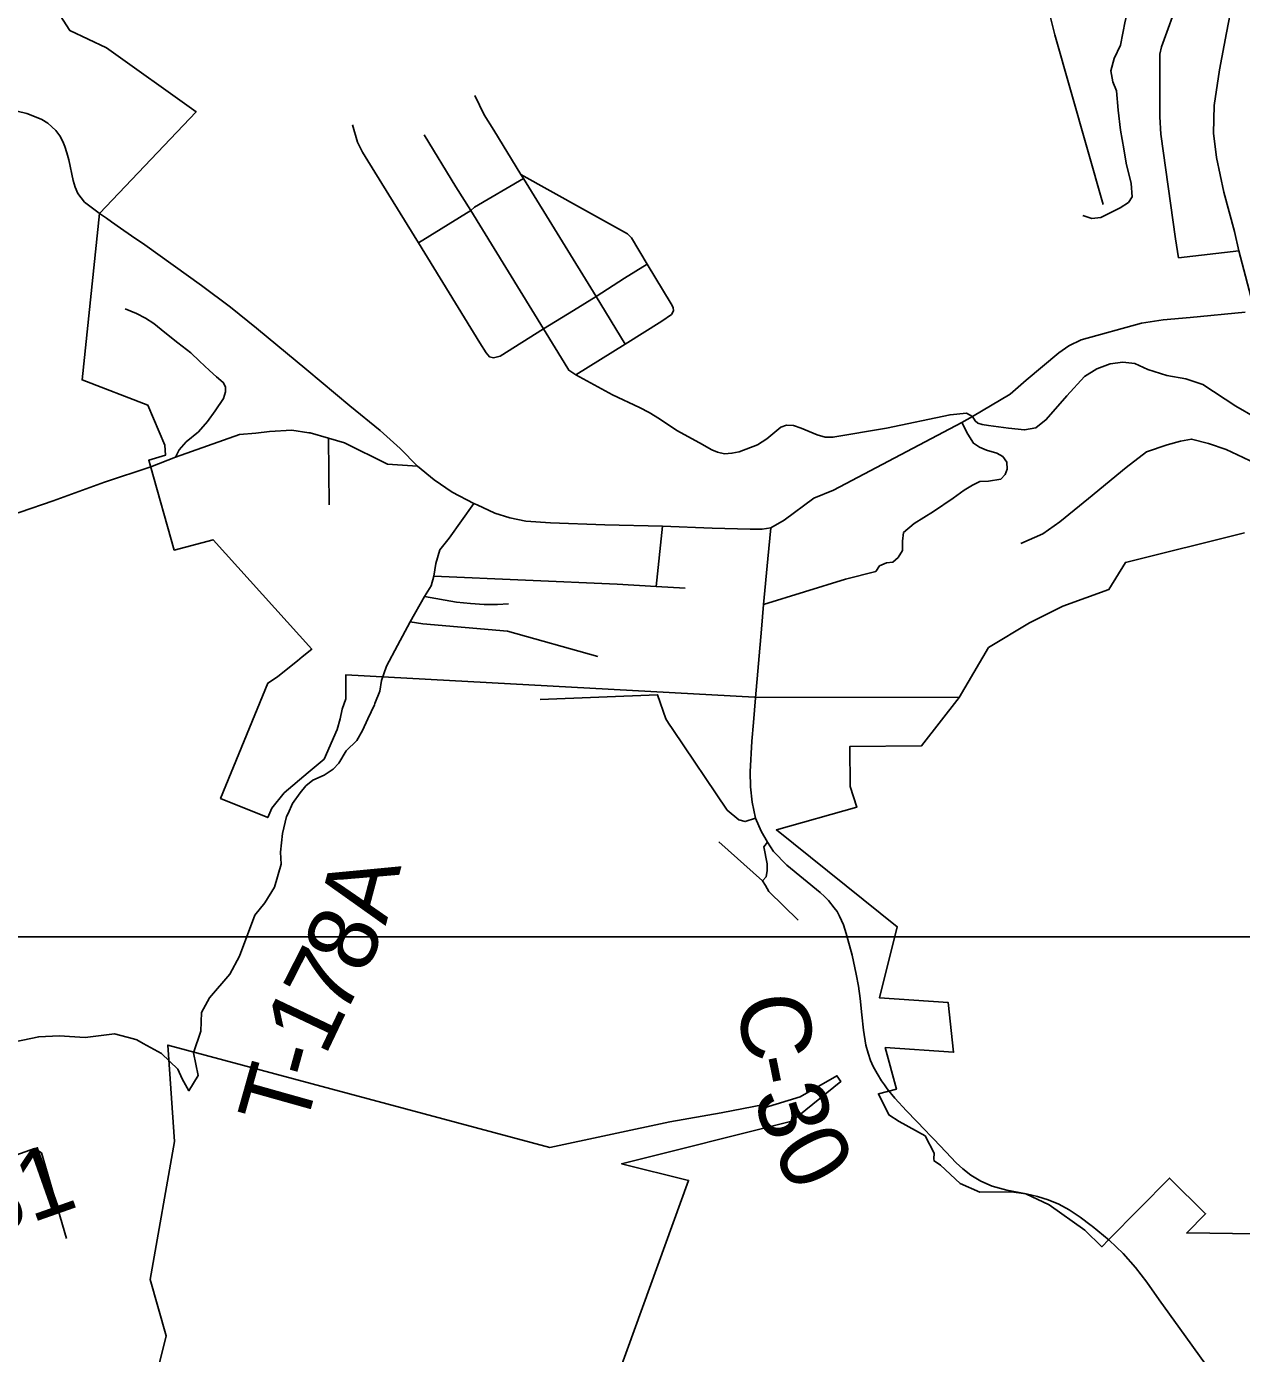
# Model space of a CAD drawing. Extents: x 2402298 to 2498138, y 789485 to 950881.
# Drawn here: x 2487007 to 2492231, y 857480 to 863186 of the extents above; entities that cross this region are included whole.
import ezdxf

# ---------------------------------------------------------------- set-up
doc = ezdxf.new("R2010")
doc.units = 0
for name, color, linetype in [('GM_X_City_Street', 7, 'Continuous'), ('GM_X_Corporation', 7, 'Continuous'), ('GM_X_County_Road', 7, 'Continuous'), ('GM_X_County_Road_Text', 7, 'Continuous'), ('GM_X_Township_Road', 7, 'Continuous'), ('GM_X_Township_Road_Text', 7, 'Continuous'), ('SH_Text', 7, 'Continuous')]:
    doc.layers.add(name, color=color, linetype=linetype)

msp = doc.modelspace()

# ---------------------------------------------------------------- linework, layer by layer
at = {"layer": 'GM_X_City_Street'}
for p, q in [((2491960.8, 862191.7), (2492219.7, 862221.5)), ((2488308.5, 861128.4), (2488305.2, 861415.9)), ((2489713.9, 860777.3), (2489742, 861037.1)), ((2490176.7, 860700), (2490528.2, 860808.9))]:
    msp.add_line(p, q, dxfattribs=at)
for points in [[(2491710.1, 862406), (2491746, 862429), (2491761.9, 862453.6), (2491757.2, 862510.5), (2491736.2, 862597.7), (2491725, 862660.2), (2491711.6, 862740.2), (2491700.9, 862825.8), (2491694.2, 862909.4), (2491678.8, 862948.3), (2491669.6, 862995.5), (2491684.5, 863048.8), (2491711.1, 863105.7), (2491731.6, 863208.3), (2491770.6, 863362), (2491857.7, 863639.9), (2491891.6, 863752.7), (2491894.6, 863789.6), (2491884.4, 863817.3), (2492057.7, 864297.1), (2492090.9, 864310.9)], [(2491637.3, 862419.8), (2491428.6, 863149.3), (2491392.8, 863292.8), (2491373.8, 863335.9), (2491315.3, 863386.7), (2491242.6, 863455.9), (2491216.9, 863490.2), (2491208.2, 863523), (2491254.2, 863763)], [(2491960.8, 862191.7), (2491947.4, 862272.2), (2491884.9, 862723.3), (2491880.8, 862797.1), (2491879.8, 862875), (2491880.8, 863067.3), (2491886.9, 863098.5), (2492115.1, 863727.6)], [(2492286.3, 861969.7), (2492219.7, 862221.5), (2492201.7, 862303.9), (2492155.6, 862473.1), (2492123.8, 862621.8), (2492111.5, 862727.4), (2492113.5, 862846.3), (2492137.1, 862999.1), (2492166.9, 863159), (2492191.5, 863284.6), (2492226.3, 863403.1), (2492309.2, 863653.8)], [(2489581.5, 861820.1), (2489457.1, 862024.7), (2489144.6, 862532.5), (2489132.7, 862549.1), (2489015.9, 862740.2), (2488975.1, 862806), (2488934.2, 862889.5)], [(2488956, 861826.2), (2488692.7, 862256.2), (2488475.2, 862608.4), (2488452.2, 862645.9), (2488430.7, 862688.9), (2488409.2, 862762.9)], [(2491075.5, 861508.6), (2491048.8, 861522.4), (2490978.6, 861516), (2490704.7, 861458.5), (2490474.3, 861419.2), (2490442, 861419.8), (2490407.3, 861430.2), (2490338.5, 861457.9), (2490304.4, 861470.5), (2490274.6, 861472), (2490250.9, 861463.4), (2490233.4, 861448.1), (2490190.7, 861413.3), (2490150.8, 861387.5), (2490071.8, 861357.4), (2490040.2, 861350.4), (2490008.2, 861348.8), (2489978.4, 861355), (2489953.8, 861365.7), (2489900.4, 861396.1), (2489803.9, 861448.7), (2489729, 861498.1), (2489684.4, 861526.4), (2489642.6, 861547.9), (2489526.8, 861601.4), (2489369.5, 861688.5), (2489339.7, 861707.7), (2489319.1, 861740.8), (2489229.4, 861886.1), (2488917.9, 862394.3), (2488853.4, 862496.9), (2488717.6, 862720.5)], [(2488692.7, 862256.2), (2488917.9, 862394.3), (2488933.3, 862408.7), (2489144.6, 862532.5)], [(2489369.5, 861688.5), (2489581.5, 861820.1), (2489739.4, 861918.4), (2489780, 861947.6), (2489788.6, 861963.3), (2489787, 861977.1), (2489779.4, 861993.7), (2489676.3, 862163.4), (2489608.8, 862277.5), (2489591, 862294.1), (2489397.8, 862401.3), (2489132.7, 862549.1)], [(2491548.6, 862373.7), (2491588.1, 862360.3), (2491626, 862363.9), (2491673.2, 862387), (2491710.1, 862406)], [(2488956, 861826.2), (2488983, 861782.9), (2488997.2, 861765.4), (2489015.6, 861761.7), (2489043.3, 861768.2), (2489229.4, 861886.1), (2489358.8, 861964.8), (2489457.1, 862024.7), (2489577.8, 862103.4), (2489676.3, 862163.4)], [(2487430.7, 861971.2), (2487479.5, 861951), (2487518.2, 861931.3), (2487554.2, 861908), (2487601.5, 861869.9), (2487657.4, 861825), (2487713.6, 861782.3), (2487751.4, 861746.7), (2487793.2, 861706.4), (2487824.5, 861679.4), (2487853.1, 861655.4), (2487862.3, 861637), (2487862, 861614.3), (2487853.4, 861585.7), (2487818.4, 861533.2), (2487784.9, 861486.8), (2487745.9, 861442.5), (2487693.4, 861399.2), (2487663.9, 861365.7), (2487648.2, 861333.5)], [(2492292.4, 861504.7), (2492206.7, 861552.8), (2492065.1, 861647), (2491991.6, 861671.4), (2491909.9, 861685.5), (2491828.2, 861711.3), (2491772.2, 861736.8), (2491721.9, 861742.7), (2491666.2, 861735.9), (2491610, 861713.2), (2491556.6, 861681.2), (2491480.4, 861597.1), (2491391.9, 861495.7), (2491346.5, 861460), (2491298.5, 861450.8), (2491229.1, 861458.8), (2491144.3, 861470.5), (2491117, 861473.9), (2491098.3, 861479.6), (2491087, 861489.9), (2491075.5, 861508.6)], [(2490528.2, 860808.9), (2490659, 860842.4), (2490675.1, 860866.3), (2490704.6, 860879), (2490731.7, 860882.9), (2490755.3, 860902.6), (2490773.8, 860932.3), (2490773.4, 860972.3), (2490777.7, 861009.8), (2490824.6, 861048.9), (2490906.8, 861100.1), (2490991.6, 861157.8), (2491039.7, 861191.3), (2491074.8, 861212.9), (2491106.9, 861228.8), (2491144.3, 861230.9), (2491196.4, 861239.5), (2491215.3, 861259.8), (2491223.9, 861282.6), (2491222.6, 861312.3), (2491205.4, 861336.3), (2491179.6, 861351), (2491135.7, 861364.3), (2491104.7, 861377.2), (2491079.3, 861394), (2491054.8, 861433.2), (2491029.4, 861483.1)], [(2491282, 860962.7), (2491377.7, 861004.5), (2491450.4, 861056.3), (2491574.1, 861156.5), (2491735.2, 861289.3), (2491823.6, 861357.2), (2491912.4, 861386.6), (2491969.3, 861403.1), (2492016.6, 861411.5), (2492089.3, 861392.4), (2492165.3, 861367.1), (2492239, 861331.9), (2492298.5, 861303.3), (2492345.5, 861274.3), (2492368.6, 861255.9)], [(2488532.9, 860373.3), (2488555, 860435.4), (2488601.9, 860523.8), (2488656.6, 860625.8), (2488717.9, 860734.7), (2488746.5, 860779.9), (2488759, 860821.8), (2488767.4, 860876.1), (2488784.7, 860934.8), (2488824.3, 860986.2), (2488930.8, 861134.8)], [(2488759, 860821.8), (2489547.2, 860788), (2489713.9, 860777.3), (2489839.9, 860770.5)], [(2488717.9, 860734.7), (2488855.9, 860710.6), (2488916.1, 860705.1), (2488974.4, 860700.7), (2489031.7, 860701), (2489079, 860703.6)], [(2488656.6, 860625.8), (2488710.7, 860617), (2489074.6, 860585.7), (2489464, 860476.8)]]:
    msp.add_lwpolyline(points, dxfattribs=at)
at = {"layer": 'GM_X_Corporation'}
for points in [[(2492243.9, 861008.7), (2491732.5, 860881.6), (2491661.5, 860764.7), (2491464, 860692.7), (2491320.5, 860621.2), (2491143.3, 860515.4), (2491017.2, 860299.8), (2490137.3, 860301.8), (2488379.9, 860397.8), (2488379.6, 860294), (2488364.6, 860250.5), (2488356.3, 860209.3), (2488342.1, 860162.4), (2488286.4, 860035.2), (2488217.5, 859977.8), (2488115.2, 859889.9), (2488062.5, 859824.8), (2488044.4, 859784.4), (2487841.3, 859866.6), (2488044.4, 860362.2), (2488086.4, 860389.4), (2488151.7, 860442.2), (2488171.9, 860458.6), (2488192.1, 860474.9), (2488233.3, 860508.2), (2487809.4, 860978.7), (2487642.3, 860934.4), (2487540.1, 861294.7), (2487532.7, 861320.6), (2487604.2, 861342.4), (2487601.2, 861385.2), (2487528.9, 861557), (2487246, 861666.2), (2487321.5, 862381.2), (2487735.8, 862819.3), (2487350.7, 863094.3), (2487192.7, 863168.5), (2487001.2, 863468.5)], [(2492488.7, 857991.7), (2491995.8, 857997.8), (2492077.3, 858080.3), (2491922.4, 858233.6), (2491661.6, 857970.2), (2491630.5, 857938.7), (2491557.8, 858010.6), (2491404.6, 858118.9), (2491304.2, 858165.8), (2491242.1, 858175), (2491106.3, 858173.4), (2491021.9, 858210.4), (2490937.1, 858289.5), (2490909.5, 858307.5), (2490908.6, 858316.1), (2490909.8, 858341.7), (2490871.6, 858414.9), (2490759, 858477.6), (2490715.3, 858505.6), (2490670.5, 858596.2), (2490747.8, 858616.9), (2490700, 858795.5), (2490993.3, 858774.9), (2490970.9, 858988.6), (2490674.7, 859009.5), (2490751, 859314.9), (2490231.4, 859730.8), (2490577.4, 859828.7), (2490549.2, 859918.3), (2490547.8, 860090.2), (2490856.1, 860092.8), (2491017.2, 860299.8), (2491143.3, 860515.4), (2491320.5, 860621.2), (2491464, 860692.7), (2491661.5, 860764.7), (2491732.5, 860881.6), (2492243.9, 861008.7)], [(2487427.3, 856831.2), (2487608, 857556), (2487538.8, 857797.2), (2487643.5, 858391.1), (2487614.5, 858806.1), (2489257.5, 858365.8), (2489774, 858475.6), (2489994.6, 858514.5), (2490179.1, 858550.4), (2490179.1, 858535.4), (2490334, 858582.7), (2490491.6, 858673.8), (2490508, 858648.6), (2490297.4, 858478.1), (2489565.8, 858295.6), (2489854, 858223.8), (2489259.5, 856584.9)]]:
    msp.add_lwpolyline(points, dxfattribs=at)
at = {"layer": 'GM_X_County_Road'}
for points in [[(2486966.6, 862821.4), (2487008.3, 862811), (2487048.8, 862796.6), (2487072.5, 862785.5), (2487098.2, 862770.1), (2487133, 862739.2), (2487150, 862715.9), (2487162.9, 862690.9), (2487171.5, 862670.3), (2487180.1, 862642.8), (2487189.5, 862611.8), (2487207, 862523.1), (2487216.1, 862495.4), (2487228.1, 862467.2), (2487257, 862430.4), (2487325, 862379.1), (2487350.9, 862361), (2487372.5, 862345.9)], [(2487372.5, 862345.9), (2487411.3, 862318.7), (2487458.9, 862285.6)], [(2487458.9, 862285.6), (2487515.2, 862246.5), (2487759.1, 862072.3), (2487884.4, 861979.2), (2487996, 861889.2), (2488212.2, 861709.8), (2488397.4, 861554.3), (2488527.2, 861448.6), (2488614.4, 861371.3), (2488688.1, 861295.1)], [(2488944.4, 861128.4), (2489021.2, 861092.6), (2489084.9, 861073.7), (2489154.6, 861059), (2489260.4, 861050.9), (2489493.9, 861042.9), (2489742, 861037.1), (2489955.7, 861028.7), (2490119.2, 861023.8), (2490170, 861023.8), (2490207.2, 861030.2), (2490265.3, 861062.3), (2490392.3, 861157.2), (2490476.5, 861192.1), (2491029.4, 861483.1), (2491075.5, 861508.6), (2491236.5, 861604.7), (2491305.9, 861664.6), (2491446, 861782.3), (2491489.3, 861812.7), (2491542.2, 861839.1), (2491801.1, 861909.8), (2491895.1, 861924.5), (2492010.7, 861933.8), (2492247.2, 861957.7)], [(2487648.2, 861333.5), (2487922.2, 861431.2), (2487992.7, 861436.9), (2488051.7, 861444.5), (2488148, 861450.2), (2488221.3, 861439.2)], [(2488221.3, 861439.2), (2488226.2, 861438.5), (2488305.2, 861415.9), (2488374.4, 861395.4), (2488558.8, 861303.2), (2488688.1, 861295.1)], [(2486362, 860751.6), (2486381.5, 860754.6), (2486436.2, 860775.4), (2486558.6, 860831.3), (2486623.4, 860874.7), (2486664.9, 860909.2), (2486708.3, 860945.4), (2486791, 861014.4), (2486825.4, 861041.1), (2486855.2, 861060.1), (2486884.8, 861070.1), (2486979, 861097.8), (2487122, 861145.4), (2487343, 861226.4), (2487541.1, 861291.8), (2487648.2, 861333.5)], [(2488688.1, 861295.1), (2488759.6, 861235.9), (2488837.5, 861183.4), (2488930.8, 861134.8), (2488944.4, 861128.4)], [(2490132.5, 860192.8), (2490141.4, 860298.8), (2490167.6, 860594.2), (2490176.7, 860700), (2490194.9, 860896.4), (2490207.2, 861030.2)], [(2490696.1, 858634.4), (2490684, 858651.4), (2490664.2, 858683.8), (2490648.4, 858713.5), (2490636.8, 858740.1), (2490626.2, 858771.5), (2490616.6, 858805.7), (2490606.7, 858870.4), (2490599.6, 858935.2), (2490591.2, 859005.8), (2490584.7, 859059.5), (2490574.6, 859110.1), (2490557, 859192.7), (2490532.1, 859284.9), (2490519.5, 859323.5), (2490502.8, 859360.8), (2490492.3, 859379.8), (2490480.6, 859396.3), (2490455.3, 859427.4), (2490438, 859445), (2490419.6, 859461.3), (2490276.3, 859579.4), (2490219.3, 859638.2), (2490193.3, 859678.3), (2490165.9, 859725.9), (2490142.2, 859781), (2490127.7, 859850.4), (2490119.9, 859915.6), (2490118.3, 859980.2), (2490125.9, 860113.3), (2490132.5, 860192.8)], [(2490871.2, 858439.8), (2490834.2, 858478.7), (2490791.2, 858523.7), (2490741.3, 858577.5), (2490708.1, 858617.3), (2490696.1, 858634.4)], [(2490908.1, 858400.9), (2490893.3, 858416.5), (2490871.2, 858439.8)], [(2491585, 858029.8), (2491537.4, 858066.1), (2491489.9, 858097.7), (2491446.4, 858121.6), (2491400.4, 858140.9), (2491354.8, 858154.7), (2491305.1, 858165.5), (2491222.5, 858181.4), (2491160.1, 858199.2), (2491110, 858220.8), (2491067, 858246.8), (2491033.6, 858273.2), (2491004.6, 858299.5), (2490959.6, 858346.4), (2490908.1, 858400.9)], [(2492175.4, 857129.2), (2492150.6, 857258.7), (2492131.5, 857324.9), (2492108.4, 857380), (2492077, 857433.6), (2491966.8, 857587.2), (2491877.8, 857710.9), (2491824, 857786.6), (2491775.8, 857848.8), (2491723.3, 857910.1), (2491662.6, 857967.3), (2491589.3, 858026.5), (2491585, 858029.8)]]:
    msp.add_lwpolyline(points, dxfattribs=at)
at = {"layer": 'GM_X_Township_Road'}
msp.add_line((2490171.6, 859512.4), (2489984, 859679.2), dxfattribs=at)
for points in [[(2488505.1, 860274.3), (2488525.6, 860327.5), (2488532.9, 860373.3)], [(2489785.6, 860162.7), (2489766.9, 860190.4), (2489756.2, 860208.9), (2489720.6, 860312.5), (2489215.6, 860292.5)], [(2488132, 859802.3), (2488151.3, 859844.2), (2488183.9, 859890.8), (2488207.4, 859920.1), (2488237.9, 859944.7), (2488286.3, 859967.1), (2488326, 859992.8), (2488349.8, 860018.5), (2488382.1, 860071.3), (2488427.6, 860115.7), (2488451.8, 860158.3), (2488475, 860208.2), (2488503.2, 860269.5), (2488505.1, 860274.3)], [(2490142.2, 859781), (2490096.8, 859767), (2490069.8, 859774.7), (2490019.7, 859816.2), (2489785.6, 860162.7)], [(2487508.3, 858813.3), (2487586.9, 858769.6), (2487658, 858702.8), (2487676.8, 858661.1), (2487705.6, 858609.5), (2487744.4, 858674.3), (2487724.7, 858772.1), (2487756.9, 858865.4), (2487759.2, 858945.2), (2487794.4, 859009.1), (2487881.2, 859110.1), (2487922.9, 859188.1), (2487988.7, 859363.8), (2488032, 859417), (2488073.7, 859485), (2488101.7, 859584.3), (2488098.8, 859635.7), (2488107.2, 859715.4), (2488125.6, 859788.4), (2488132, 859802.3)], [(2490184.1, 859491.3), (2490171.6, 859512.4), (2490187, 859529.7), (2490192.3, 859557.2), (2490191.3, 859585.2), (2490177.4, 859658.5), (2490193.3, 859678.3)], [(2490325.4, 859343.5), (2490199.1, 859466), (2490184.1, 859491.3)], [(2486035.1, 857997.6), (2486214.6, 858067.5), (2486240.7, 858075.6), (2486313.5, 858134.3), (2486353.4, 858229.9), (2486370.4, 858319.7), (2486392.7, 858404.8), (2486408.5, 858479.3), (2486440.2, 858559.7), (2486539.9, 858657.1), (2486595.7, 858693.5), (2486751.8, 858764.5), (2486796.4, 858770.3), (2486915.5, 858811.4), (2487059.8, 858841.9), (2487146.7, 858846), (2487259.3, 858837.8), (2487385.7, 858854.2), (2487466.8, 858832), (2487482, 858827.9), (2487508.3, 858813.3)], [(2487178.3, 857973.9), (2487071.7, 858342.1), (2487041.1, 858360.8), (2486240.7, 858075.6)]]:
    msp.add_lwpolyline(points, dxfattribs=at)
at = {"layer": 'SH_Text'}
msp.add_lwpolyline([(2448187, 889728.7), (2496836.3, 889728.7), (2496836.3, 859271.1), (2448187, 859271.1)], close=True, dxfattribs=at)

# ---------------------------------------------------------------- texts
at = {"layer": 'GM_X_County_Road_Text'}
for s, rotation, p in [('C', 277.1023, (2490063.3, 859011.4)), ('-', 281.5442, (2490097.9, 858741.8)), ('3', 287.0547, (2490130.3, 858590.6)), ('0', 298.2877, (2490209.2, 858354.8))]:
    msp.add_text(s, height=300, rotation=rotation, dxfattribs=at).set_placement(p)
at = {"layer": 'GM_X_Township_Road_Text'}
for s, rotation, p in [('A', 75.1539, (2488551.2, 859317.1)), ('8', 66.4854, (2488461.2, 859100.9)), ('7', 63.0021, (2488368.8, 858918.2)), ('1', 64.5754, (2488290.4, 858753.3)), ('-', 74.5661, (2488262.5, 858647.5)), ('T', 74.3077, (2488201.4, 858430)), ('T-231', 19.4179, (2486249, 857765.8))]:
    msp.add_text(s, height=300, rotation=rotation, dxfattribs=at).set_placement(p)

doc.saveas('drawing.dxf')
